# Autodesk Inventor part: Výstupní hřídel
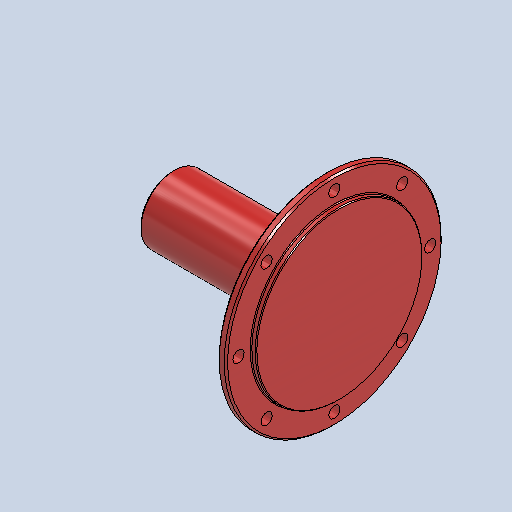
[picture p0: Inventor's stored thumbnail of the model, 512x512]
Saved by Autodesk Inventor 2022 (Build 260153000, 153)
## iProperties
Created: 2025-05
Part Number: Výstupní hřídel
Material: Všeobecné
Document SubType Name: Modeling
Designer: jbart
Density: 1 g/cm^3
Appearance: Oranžovo-červená
Mass: 1634.63 g
Surface Area: 1615.74 cm^2
Volume: 1634.63 cm^3
Author: jbart
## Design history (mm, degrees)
sketch "Náčrt1"
  geometry: L1 (0, 0)-(200, 0); L2 (194, 130)-(194, 100); L3 (194, 100)-(200, 100); L4 (200, 100)-(200, 0); L5 (194, 130)-(184, 130); L6 (184, 130)-(184, 40); L7 (184, 40)-(0, 40); L8 (0, 40)-(0, 0); 1 further point
  constraints: 16 end point, 5 perpendicular, 2 horizontal, 1 midpoint, 1 point on line, 1 vertical, 1 vertical alignment
  dimensions: "d0" = 200 distance of L1.start L1.end; "d2" = 6 distance of L2.end L3.end; "d3" = 10 distance of L2.start L5.end; "d4" = 200 diameter of L3 L1; "d5" = 260 diameter of L5 L1; "d6" = 80 diameter of L7 L1
revolve "Rotace1" sketch "Náčrt1" stored, may be unused: angle "d7" = 90 deg
fillet "Zaoblení1" dims "d8" = 10
sketch "Náčrt2" dims "d9" = 230
  geometry: L1 (0, 0)-(0, 115); 2 further points
  constraints: 2 coincident, 2 end point, 1 vertical, 1 vertical alignment, 2 other
hole "Díra1" sketch "Náčrt2" at (0, 115) diameter "d10" = 13.5; stored, may be unused: countersink angle "d14" = 90 deg, drill point angle "d16" = 118 deg; dims "d11" = 15, "d12" = 4, "d13" = 2, "d15" = 20
pattern_circular "Kruhové pole1" dims angle "d18" = 360 deg
chamfer "Zkosení1" distance "d20" = 2; stored, may be unused: second distance "d21" = 2, angle "d22" = 45 deg
chamfer "Zkosení2" distance "d23" = 1; stored, may be unused: second distance "d24" = 2, angle "d25" = 45 deg
fillet "Zaoblení2" dims "d26" = 1
node "Těleso1"
